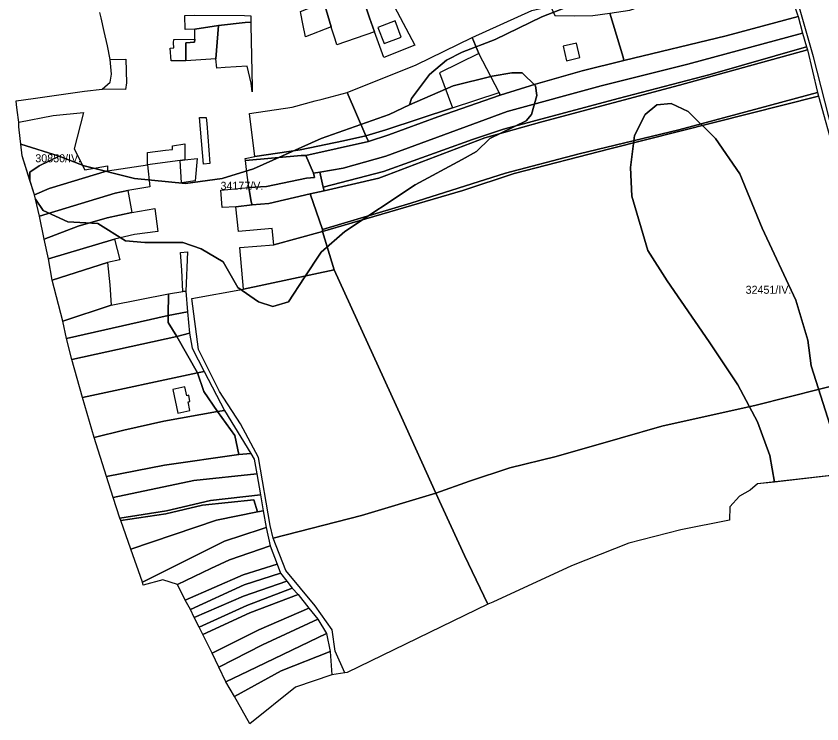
# Model space of a CAD drawing. Extents: x -532083 to -529270, y -1180561 to -1176456.
# Drawn here: x -532083 to -531579, y -1178876 to -1178433 of the extents above; entities that cross this region are included whole.
import ezdxf

# ---------------------------------------------------------------- set-up
doc = ezdxf.new("R2010")
doc.units = 0
for name, color, linetype in [('95560013', 7, 'Continuous'), ('95590013', 7, 'Continuous'), ('95610013', 7, 'Continuous'), ('95660013', 7, 'Continuous')]:
    doc.layers.add(name, color=color, linetype=linetype)

msp = doc.modelspace()

# ---------------------------------------------------------------- linework, layer by layer
at = {"layer": '95560013'}
for points in [[(-531547.8033, -1178576.86445), (-531567.7783, -1178522.58045), (-531572.5603, -1178505.32245), (-531584.2383, -1178458.86945), (-531591.8903, -1178432.61345), (-531602.2653, -1178396.57645), (-531604.7423, -1178392.64145), (-531576.9383, -1178389.59645), (-531567.2013, -1178431.02045), (-531545.1963, -1178517.96245), (-531535.0483, -1178553.58645), (-531517.1773, -1178614.23745), (-531494.4363, -1178669.65645), (-531470.1583, -1178727.24745), (-531454.4793, -1178763.65545), (-531462.1273, -1178770.74145), (-531480.8163, -1178726.71045), (-531489.0293, -1178711.65445), (-531517.1343, -1178652.33845), (-531534.5643, -1178611.81145)], [(-531852.9093, -1178459.31445), (-531858.6763, -1178443.37145), (-531861.7713, -1178434.62345), (-531867.5383, -1178417.26945), (-531854.3163, -1178412.33045), (-531846.4393, -1178427.28645), (-531833.4983, -1178451.69545)], [(-531841.9533, -1178446.51645), (-531845.8643, -1178436.42445), (-531856.5143, -1178440.55245), (-531852.6033, -1178450.64345)], [(-531797.4043, -1178510.54745), (-531853.1373, -1178530.52845), (-531890.7863, -1178540.43245), (-531892.7783, -1178531.04145), (-531878.3643, -1178528.46845), (-531851.6523, -1178520.96645), (-531793.2423, -1178499.53045), (-531775.7903, -1178493.10045), (-531717.0233, -1178477.02345), (-531662.8873, -1178463.44745), (-531591.1313, -1178444.14245), (-531588.6623, -1178452.67145), (-531648.9653, -1178470.01645), (-531706.5083, -1178484.98045), (-531778.1553, -1178504.03645)], [(-531836.0783, -1178550.36045), (-531891.1843, -1178566.80545), (-531898.9533, -1178544.62845), (-531890.1883, -1178542.63045), (-531856.0473, -1178534.79445), (-531850.8993, -1178532.77445), (-531789.7483, -1178509.55845), (-531754.0303, -1178499.60645), (-531668.0423, -1178476.71645), (-531588.1143, -1178454.59745), (-531581.8053, -1178481.28545), (-531618.1033, -1178490.98145), (-531668.4963, -1178504.43445), (-531730.7163, -1178519.44845), (-531776.7933, -1178531.51845)], [(-531905.1193, -1178517.08045), (-531933.4183, -1178521.18745), (-531936.7993, -1178494.40745), (-531910.1023, -1178490.30145), (-531895.6863, -1178486.37445), (-531891.4143, -1178485.30245), (-531875.7613, -1178481.16445), (-531864.0383, -1178508.23145), (-531878.0653, -1178511.36845)], [(-531774.0273, -1178715.80545), (-531799.2343, -1178724.04445), (-531820.4623, -1178731.61145), (-531841.8493, -1178684.12545), (-531883.8143, -1178591.98045), (-531891.1843, -1178568.00445), (-531803.5013, -1178542.41145), (-531771.5103, -1178531.81345), (-531711.5453, -1178516.50245), (-531581.2573, -1178483.48645), (-531560.8443, -1178556.78845), (-531548.5463, -1178586.00545), (-531524.2743, -1178648.65845), (-531560.8503, -1178661.55945), (-531620.2603, -1178676.52945), (-531679.0953, -1178689.77145), (-531705.2123, -1178697.25645), (-531745.1383, -1178708.70345)], [(-531965.6323, -1178526.00745), (-531968.1243, -1178496.72845), (-531963.8523, -1178496.72845), (-531963.4963, -1178500.65645), (-531961.5393, -1178525.65045)], [(-531890.1883, -1178542.63045), (-531898.9533, -1178544.62845), (-531924.6473, -1178550.62145), (-531935.2043, -1178551.42145), (-531935.8023, -1178549.62245), (-531937.1963, -1178540.63245), (-531926.2413, -1178540.03245), (-531901.1443, -1178534.83745), (-531896.1643, -1178534.23845), (-531896.7613, -1178531.64145), (-531892.7783, -1178531.04145), (-531890.7863, -1178540.43245)], [(-531935.2043, -1178551.42145), (-531945.3633, -1178552.61945), (-531953.8683, -1178552.99945), (-531954.6583, -1178542.25345), (-531937.1963, -1178540.63245), (-531935.8023, -1178549.62245)], [(-531883.8143, -1178591.98045), (-531940.5823, -1178604.16745), (-531942.7733, -1178577.99445), (-531921.6603, -1178576.39545), (-531891.1843, -1178568.00445)], [(-531987.5833, -1178620.60945), (-532051.2263, -1178634.89945), (-532053.5293, -1178624.00745), (-532023.2493, -1178614.05745), (-531987.5393, -1178606.94645)], [(-531975.6063, -1178618.17645), (-531987.5833, -1178620.60945), (-531987.5393, -1178606.94645), (-531978.5783, -1178605.47045), (-531976.5723, -1178605.33645)], [(-531982.2773, -1178633.68745), (-531987.5833, -1178624.86745), (-531987.5833, -1178620.60945), (-531975.6063, -1178618.17645), (-531974.2423, -1178631.71045)], [(-531982.2773, -1178633.68745), (-532047.9363, -1178648.10045), (-532051.2263, -1178634.89945), (-531987.5833, -1178620.60945), (-531987.5833, -1178624.86745)], [(-531969.3903, -1178656.49845), (-532041.2583, -1178671.72145), (-532047.9363, -1178648.10045), (-531982.2773, -1178633.68745)], [(-531735.5853, -1178777.07045), (-531784.7043, -1178799.66545), (-531787.9603, -1178801.02645), (-531802.3493, -1178770.63545), (-531820.4623, -1178731.61145), (-531799.2343, -1178724.04445), (-531774.0273, -1178715.80545), (-531745.1383, -1178708.70345), (-531705.2123, -1178697.25645), (-531679.0953, -1178689.77145), (-531620.2603, -1178676.52945), (-531560.8503, -1178661.55945), (-531524.2743, -1178648.65845), (-531494.4093, -1178711.65445), (-531619.2903, -1178725.85845), (-531623.8203, -1178729.83545), (-531630.6173, -1178733.52845), (-531636.5633, -1178740.06145), (-531636.8473, -1178748.58345), (-531667.1463, -1178754.54945), (-531699.7633, -1178762.91345)], [(-532015.2983, -1178692.15745), (-532033.9303, -1178696.89445), (-532041.2583, -1178671.72145), (-531969.3903, -1178656.49845), (-531965.3283, -1178668.02345), (-531956.8683, -1178680.48845), (-531990.4453, -1178686.58745)], [(-531981.5183, -1178681.52145), (-531974.0463, -1178679.92845), (-531975.1943, -1178674.54045), (-531974.0173, -1178674.28945), (-531974.8343, -1178670.45745), (-531976.0473, -1178670.71545), (-531977.2273, -1178665.18145), (-531984.6633, -1178666.76645)], [(-531989.9163, -1178714.16845), (-532026.1583, -1178721.17545), (-532033.9303, -1178696.89445), (-532015.2983, -1178692.15745), (-531990.4453, -1178686.58745), (-531956.8683, -1178680.48845), (-531946.0283, -1178695.60445), (-531943.3843, -1178707.53845)], [(-531971.6733, -1178723.71645), (-532021.9383, -1178734.31845), (-532026.1583, -1178721.17545), (-531989.9163, -1178714.16845), (-531943.3843, -1178707.53845), (-531935.9813, -1178706.74345), (-531933.8663, -1178710.45645), (-531932.2803, -1178719.47245)], [(-531961.0983, -1178736.18045), (-531988.5943, -1178742.54545), (-532017.8143, -1178747.18445), (-532021.9383, -1178734.31845), (-531971.6733, -1178723.71645), (-531932.2803, -1178719.47245), (-531929.9003, -1178732.73345)], [(-531931.7793, -1178743.24245), (-531957.4483, -1178748.54345), (-532011.0023, -1178766.68145), (-532017.2133, -1178748.59145), (-531989.1573, -1178744.50445), (-531966.2563, -1178739.20345), (-531934.0443, -1178735.66945)], [(-531952.4153, -1178761.66945), (-531976.5743, -1178773.78645), (-532003.7893, -1178787.18245), (-532011.0023, -1178766.68145), (-531957.4483, -1178748.54345), (-531931.7793, -1178743.24245), (-531928.2563, -1178742.73745), (-531926.4953, -1178753.08745), (-531929.5143, -1178754.09645)], [(-531960.9383, -1178778.74245), (-531981.7493, -1178788.58945), (-531990.9663, -1178785.77545), (-532003.1883, -1178789.19245), (-532003.7893, -1178787.18245), (-531976.5743, -1178773.78645), (-531952.4153, -1178761.66945), (-531929.5143, -1178754.09645), (-531926.4953, -1178753.08745), (-531923.9783, -1178764.44645), (-531949.3953, -1178773.28145)], [(-531919.4483, -1178776.05845), (-531940.8393, -1178782.62145), (-531976.9553, -1178798.42145), (-531981.7493, -1178788.58945), (-531960.9383, -1178778.74245), (-531949.3953, -1178773.28145), (-531923.9783, -1178764.44645)], [(-531940.0843, -1178788.93145), (-531973.6823, -1178804.37345), (-531976.9553, -1178798.42145), (-531940.8393, -1178782.62145), (-531919.4483, -1178776.05845), (-531917.4353, -1178781.61145)], [(-531940.5873, -1178795.99945), (-531971.4313, -1178809.29945), (-531973.6823, -1178804.37345), (-531940.0843, -1178788.93145), (-531917.4353, -1178781.61145), (-531913.4093, -1178786.66045)], [(-531968.3623, -1178815.25145), (-531971.4313, -1178809.29945), (-531940.5873, -1178795.99945), (-531913.4093, -1178786.66045), (-531910.1373, -1178790.95145), (-531938.5743, -1178801.80545)], [(-531965.9073, -1178819.97245), (-531968.3623, -1178815.25145), (-531938.5743, -1178801.80545), (-531910.1373, -1178790.95145), (-531906.3623, -1178794.99045), (-531936.5613, -1178806.34945)], [(-531960.1783, -1178831.67145), (-531965.9073, -1178819.97245), (-531936.5613, -1178806.34945), (-531906.3623, -1178794.99045), (-531899.8193, -1178803.57245), (-531931.0243, -1178816.95145)], [(-531956.0863, -1178840.29145), (-531960.1783, -1178831.67145), (-531931.0243, -1178816.95145), (-531899.8193, -1178803.57245), (-531894.0313, -1178810.38845), (-531928.7593, -1178826.29145)], [(-531956.0863, -1178840.29145), (-531928.7593, -1178826.29145), (-531894.0313, -1178810.38845), (-531888.7463, -1178819.22345), (-531937.5673, -1178842.95145), (-531951.5853, -1178849.52745)], [(-531937.5673, -1178842.95145), (-531888.7463, -1178819.22345), (-531886.4813, -1178830.58245), (-531916.9323, -1178842.69945), (-531946.2653, -1178858.76345), (-531951.5853, -1178849.52745)], [(-531946.2653, -1178858.76345), (-531916.9323, -1178842.69945), (-531886.4813, -1178830.58245), (-531885.2943, -1178845.21745), (-531908.0053, -1178852.81145), (-531936.6493, -1178875.79945)]]:
    msp.add_lwpolyline(points, close=True, dxfattribs=at)
at = {"layer": '95590013'}
for points in [[(-531638.8773, -1178445.75845), (-531702.8643, -1178461.11745), (-531703.3483, -1178459.17745), (-531711.5683, -1178431.53145), (-531699.1573, -1178429.75345), (-531687.7133, -1178425.87345), (-531675.7863, -1178421.83145), (-531658.7493, -1178415.49345), (-531643.1323, -1178409.09145), (-531627.1083, -1178403.91545), (-531605.9233, -1178397.92145), (-531594.6293, -1178432.08645), (-531593.8693, -1178433.61245)], [(-531885.8243, -1178440.12545), (-531889.9033, -1178426.01645), (-531890.4663, -1178424.88845), (-531867.5383, -1178417.26945), (-531861.7713, -1178434.62345), (-531858.6763, -1178443.37145), (-531882.1343, -1178451.37245), (-531883.2923, -1178447.78345), (-531885.2613, -1178441.67745)], [(-531901.8593, -1178446.33445), (-531903.4343, -1178438.26145), (-531904.6723, -1178431.80145), (-531904.9533, -1178430.53145), (-531890.4663, -1178424.88845), (-531889.9033, -1178426.01645), (-531885.8243, -1178440.12545)], [(-531702.8643, -1178461.11745), (-531728.8983, -1178467.63045), (-531758.0933, -1178476.06145), (-531780.2113, -1178482.93945), (-531780.8753, -1178481.16445), (-531793.4823, -1178456.75945), (-531797.6843, -1178446.77645), (-531760.3053, -1178429.91445), (-531748.6383, -1178427.32845), (-531745.8983, -1178433.14845), (-531733.9713, -1178433.31045), (-531722.2053, -1178432.98645), (-531711.5683, -1178431.53145), (-531703.3483, -1178459.17745)], [(-531956.2163, -1178439.34245), (-531971.0443, -1178441.67145), (-531977.1213, -1178441.73145), (-531977.2733, -1178433.09545), (-531971.4903, -1178432.94645), (-531939.9043, -1178433.09545), (-531936.0483, -1178433.24445), (-531936.0483, -1178437.26045), (-531939.6073, -1178437.40845)], [(-531591.1313, -1178444.14245), (-531662.8873, -1178463.44745), (-531717.0233, -1178477.02345), (-531775.7903, -1178493.10045), (-531793.2423, -1178499.53045), (-531851.6523, -1178520.96645), (-531878.3643, -1178528.46845), (-531892.7783, -1178531.04145), (-531896.7613, -1178531.64145), (-531901.5423, -1178520.65245), (-531862.4903, -1178511.78145), (-531849.6623, -1178507.56545), (-531819.1393, -1178496.47245), (-531780.2113, -1178482.93945), (-531758.0933, -1178476.06145), (-531728.8983, -1178467.63045), (-531702.8643, -1178461.11745), (-531638.8773, -1178445.75845), (-531593.8693, -1178433.61245)], [(-531957.9013, -1178460.06245), (-531976.6883, -1178461.30845), (-531976.6883, -1178450.09445), (-531971.0993, -1178449.78345), (-531970.9833, -1178447.89745), (-531971.0443, -1178441.67145), (-531956.2163, -1178439.34245)], [(-531938.3343, -1178464.73245), (-531952.0643, -1178465.50445), (-531957.3253, -1178465.89045), (-531957.9013, -1178460.06245), (-531956.2163, -1178439.34245), (-531939.6073, -1178437.40845), (-531936.0483, -1178437.26045), (-531936.0063, -1178439.06445), (-531935.0913, -1178477.93645), (-531935.0913, -1178480.71745), (-531935.8473, -1178475.40845)], [(-531809.8493, -1178490.70445), (-531851.6523, -1178504.45945), (-531864.0383, -1178508.23145), (-531875.7613, -1178481.16445), (-531832.6313, -1178463.85945), (-531797.6843, -1178446.77645), (-531793.4823, -1178456.75945), (-531818.0333, -1178468.96245)], [(-531976.6883, -1178461.30845), (-531985.8493, -1178461.30845), (-531986.3153, -1178453.52145), (-531984.1413, -1178453.36545), (-531984.2963, -1178450.25045), (-531984.2093, -1178448.02745), (-531970.9833, -1178447.89745), (-531971.0993, -1178449.78345), (-531976.6883, -1178450.09445)], [(-531738.6303, -1178461.41845), (-531730.2923, -1178459.39145), (-531732.5033, -1178450.29545), (-531740.8413, -1178452.32245)], [(-532014.3303, -1178479.26545), (-532028.8773, -1178479.10845), (-532023.9863, -1178474.68045), (-532023.1513, -1178469.65345), (-532023.8673, -1178460.55845), (-532014.0473, -1178460.31845), (-532013.7863, -1178475.21845)], [(-532025.4953, -1178530.14745), (-532061.9303, -1178541.24845), (-532071.0983, -1178545.25545), (-532078.9283, -1178520.83645), (-532080.9713, -1178502.73445), (-532080.9713, -1178499.83145), (-532059.5473, -1178495.65045), (-532040.4783, -1178493.77145), (-532046.4373, -1178516.31445), (-532039.7973, -1178529.63545), (-532025.6653, -1178527.07345)], [(-531980.0923, -1178523.59945), (-532000.5373, -1178526.43645), (-532000.5473, -1178521.09345), (-532000.4673, -1178518.70545), (-531989.2273, -1178517.27245), (-531984.8773, -1178516.83645), (-531984.8773, -1178514.43645), (-531977.2643, -1178513.34545), (-531977.2643, -1178523.38145)], [(-531970.7393, -1178536.47245), (-531979.2223, -1178537.56245), (-531980.0923, -1178523.59945), (-531977.2643, -1178523.38145), (-531969.4343, -1178522.50845)], [(-531901.1443, -1178534.83745), (-531926.2413, -1178540.03245), (-531937.1963, -1178540.63245), (-531938.4013, -1178531.18445), (-531939.2913, -1178523.68645), (-531904.5303, -1178520.65245), (-531901.5423, -1178520.65245), (-531896.7613, -1178531.64145), (-531896.1643, -1178534.23845)], [(-532020.7653, -1178544.10845), (-532068.0013, -1178558.59245), (-532071.0983, -1178545.25545), (-532061.9303, -1178541.24845), (-532025.4953, -1178530.14745), (-532000.5373, -1178526.43645), (-531999.0723, -1178540.15745), (-532012.8223, -1178542.37745)], [(-532025.7683, -1178559.59845), (-532043.8213, -1178564.83445), (-532065.2343, -1178572.86745), (-532068.0013, -1178558.59245), (-532020.7653, -1178544.10845), (-532012.8223, -1178542.37745), (-532010.4523, -1178556.17045)], [(-531891.1843, -1178568.00445), (-531921.6603, -1178576.39545), (-531922.6563, -1178566.20645), (-531943.7693, -1178568.00445), (-531945.3633, -1178552.61945), (-531935.2043, -1178551.42145), (-531924.6473, -1178550.62145), (-531898.9533, -1178544.62845), (-531891.1843, -1178566.80545)], [(-532021.2003, -1178572.90745), (-532062.4673, -1178585.16045), (-532065.2343, -1178572.86745), (-532043.8213, -1178564.83445), (-532025.7683, -1178559.59845), (-532010.4523, -1178556.17045), (-531995.9113, -1178553.79245), (-531994.0123, -1178568.10745), (-532008.5853, -1178569.85245)], [(-532025.5233, -1178587.49345), (-532060.0953, -1178598.44445), (-532062.4673, -1178585.16045), (-532021.2003, -1178572.90745), (-532017.9383, -1178585.77945)], [(-531979.1133, -1178592.32345), (-531979.8743, -1178581.19745), (-531975.5243, -1178580.76145), (-531976.5723, -1178605.33645), (-531978.5783, -1178605.47045)], [(-532023.2493, -1178614.05745), (-532053.5293, -1178624.00745), (-532060.0953, -1178598.44445), (-532025.5233, -1178587.49345), (-532024.1853, -1178601.44645)]]:
    msp.add_lwpolyline(points, close=True, dxfattribs=at)
at = {"layer": '95610013'}
for points in [[(-531850.8993, -1178532.77445), (-531856.0473, -1178534.79445), (-531890.1883, -1178542.63045), (-531890.7863, -1178540.43245), (-531853.1373, -1178530.52845), (-531797.4043, -1178510.54745), (-531778.1553, -1178504.03645), (-531706.5083, -1178484.98045), (-531648.9653, -1178470.01645), (-531588.6623, -1178452.67145), (-531588.1143, -1178454.59745), (-531668.0423, -1178476.71645), (-531754.0303, -1178499.60645), (-531789.7483, -1178509.55845)], [(-531771.5103, -1178531.81345), (-531803.5013, -1178542.41145), (-531891.1843, -1178568.00445), (-531891.1843, -1178566.80545), (-531836.0783, -1178550.36045), (-531776.7933, -1178531.51845), (-531730.7163, -1178519.44845), (-531668.4963, -1178504.43445), (-531618.1033, -1178490.98145), (-531581.8053, -1178481.28545), (-531581.2573, -1178483.48645), (-531711.5453, -1178516.50245)], [(-531862.4903, -1178511.78145), (-531864.0383, -1178508.23145), (-531851.6523, -1178504.45945), (-531809.8493, -1178490.70445), (-531780.8753, -1178481.16445), (-531780.2113, -1178482.93945), (-531819.1393, -1178496.47245), (-531849.6623, -1178507.56545)], [(-531862.4903, -1178511.78145), (-531901.5423, -1178520.65245), (-531904.5303, -1178520.65245), (-531939.2913, -1178523.68645), (-531939.4693, -1178522.43645), (-531933.4183, -1178521.18745), (-531905.1193, -1178517.08045), (-531878.0653, -1178511.36845), (-531864.0383, -1178508.23145)], [(-531866.7653, -1178745.56645), (-531921.9973, -1178759.72845), (-531923.8653, -1178751.81445), (-531931.2863, -1178709.21245), (-531942.3853, -1178688.18245), (-531955.6433, -1178668.07945), (-531968.5923, -1178641.79245), (-531972.8503, -1178609.96245), (-531940.5823, -1178604.16745), (-531883.8143, -1178591.98045), (-531841.8493, -1178684.12545), (-531820.4623, -1178731.61145)], [(-531969.3903, -1178656.49845), (-531982.2773, -1178633.68745), (-531974.2423, -1178631.71045), (-531972.7253, -1178640.98645), (-531965.1453, -1178655.58545)], [(-531956.8683, -1178680.48845), (-531965.3283, -1178668.02345), (-531969.3903, -1178656.49845), (-531965.1453, -1178655.58545), (-531952.3733, -1178679.95745)], [(-531935.9813, -1178706.74345), (-531943.3843, -1178707.53845), (-531946.0283, -1178695.60445), (-531956.8683, -1178680.48845), (-531952.3733, -1178679.95745)], [(-531928.2563, -1178742.73745), (-531931.7793, -1178743.24245), (-531934.0443, -1178735.66945), (-531966.2563, -1178739.20345), (-531989.1573, -1178744.50445), (-532017.2133, -1178748.59145), (-532017.8143, -1178747.18445), (-531988.5943, -1178742.54545), (-531961.0983, -1178736.18045), (-531929.9003, -1178732.73345)], [(-531787.9603, -1178801.02645), (-531875.8823, -1178843.78045), (-531877.3153, -1178843.98645), (-531883.2103, -1178830.33045), (-531885.2233, -1178816.95145), (-531895.7933, -1178802.05845), (-531914.1633, -1178779.84445), (-531921.9973, -1178759.72845), (-531866.7653, -1178745.56645), (-531820.4623, -1178731.61145), (-531802.3493, -1178770.63545)]]:
    msp.add_lwpolyline(points, close=True, dxfattribs=at)
at = {"layer": '95660013'}
for points in [[(-531711.1873, -1178417.00045), (-531754.1253, -1178434.00045), (-531783.3753, -1178448.00045), (-531803.8123, -1178456.00045), (-531813.6253, -1178461.00045), (-531824.3123, -1178470.00045), (-531835.6253, -1178485.00045), (-531836.8123, -1178489.00045), (-531849.5003, -1178495.00045), (-531892.0003, -1178510.00045), (-531934.3753, -1178529.00045), (-531954.0003, -1178535.00045), (-531976.8753, -1178538.00045), (-532008.6873, -1178535.00045), (-532040.1253, -1178527.00045), (-532055.6873, -1178521.00045), (-532079.7683, -1178513.39645), (-532080.9713, -1178502.73445), (-532080.9713, -1178499.83145), (-532081.9923, -1178492.14745), (-532082.3333, -1178488.73245), (-532082.6733, -1178486.34145), (-532071.9463, -1178484.85345), (-532039.8533, -1178480.42445), (-532028.8773, -1178479.10845), (-532023.9863, -1178474.68045), (-532023.1513, -1178469.65345), (-532023.8673, -1178460.55845), (-532025.6563, -1178452.06045), (-532027.6843, -1178443.08445), (-532029.5063, -1178434.54645), (-532030.3663, -1178431.20345)], [(-531569.6253, -1178703.00045), (-531585.8753, -1178652.00045), (-531587.8753, -1178636.00045), (-531595.3123, -1178611.00045), (-531616.5003, -1178566.00045), (-531630.3753, -1178532.00045), (-531645.5003, -1178510.00045), (-531662.6253, -1178493.00045), (-531673.3123, -1178488.00045), (-531682.1873, -1178489.00045), (-531689.6253, -1178495.00045), (-531696.1253, -1178508.00045), (-531698.6253, -1178528.00045), (-531697.8123, -1178546.00045), (-531687.8753, -1178580.00045), (-531675.6873, -1178599.00045), (-531649.6253, -1178637.00045), (-531631.6253, -1178664.00045), (-531619.3753, -1178687.00045), (-531611.6253, -1178708.00045), (-531608.6883, -1178724.65245), (-531619.2903, -1178725.85845), (-531623.8203, -1178729.83545), (-531630.6173, -1178733.52845), (-531636.5633, -1178740.06145), (-531636.8473, -1178748.58345), (-531667.1463, -1178754.54945), (-531699.7633, -1178762.91345), (-531735.5853, -1178777.07045), (-531784.7043, -1178799.66545), (-531787.9603, -1178801.02645), (-531875.8823, -1178843.78045), (-531877.3153, -1178843.98645), (-531885.2943, -1178845.21745), (-531908.0053, -1178852.81145), (-531936.6493, -1178875.79945), (-531946.2653, -1178858.76345), (-531951.5853, -1178849.52745), (-531956.0863, -1178840.29145), (-531960.1783, -1178831.67145), (-531965.9073, -1178819.97245), (-531968.3623, -1178815.25145), (-531971.4313, -1178809.29945), (-531973.6823, -1178804.37345), (-531976.9553, -1178798.42145), (-531981.7493, -1178788.58945), (-531990.9663, -1178785.77545), (-532003.1883, -1178789.19245), (-532003.7893, -1178787.18245), (-532011.0023, -1178766.68145), (-532017.2133, -1178748.59145), (-532017.8143, -1178747.18445), (-532021.9383, -1178734.31845), (-532026.1583, -1178721.17545), (-532033.9303, -1178696.89445), (-532041.2583, -1178671.72145), (-532047.9363, -1178648.10045), (-532051.2263, -1178634.89945), (-532053.5293, -1178624.00745), (-532060.0953, -1178598.44445), (-532062.4673, -1178585.16045), (-532065.2343, -1178572.86745), (-532068.0013, -1178558.59245), (-532070.4903, -1178547.87245), (-532065.8123, -1178555.00045), (-532050.3123, -1178562.00045), (-532031.6253, -1178563.00045), (-532014.3753, -1178574.00045), (-532002.1873, -1178575.00045), (-531978.5003, -1178575.00045), (-531967.1253, -1178579.00045), (-531953.1873, -1178587.00045), (-531944.1873, -1178603.00045), (-531931.1253, -1178612.00045), (-531922.1873, -1178615.00045), (-531912.3753, -1178612.00045), (-531902.6253, -1178597.00045), (-531892.0003, -1178581.00045), (-531877.3123, -1178568.00045), (-531833.1873, -1178539.00045), (-531803.8123, -1178523.00045), (-531794.8753, -1178518.00045), (-531786.6873, -1178510.00045), (-531763.8123, -1178499.00045), (-531760.6253, -1178495.00045), (-531757.3123, -1178483.00045), (-531758.1253, -1178477.00045), (-531766.3123, -1178469.00045), (-531772.8123, -1178469.00045), (-531785.1253, -1178471.00045), (-531809.6253, -1178477.00045), (-531836.8123, -1178489.00045), (-531835.6253, -1178485.00045), (-531824.3123, -1178470.00045), (-531813.6253, -1178461.00045), (-531803.8123, -1178456.00045), (-531783.3753, -1178448.00045), (-531754.1253, -1178434.00045), (-531711.1873, -1178417.00045)]]:
    msp.add_lwpolyline(points, dxfattribs=at)
for points in [[(-532065.8123, -1178555.00045), (-532070.4903, -1178547.87245), (-532071.0983, -1178545.25545), (-532074.0003, -1178536.20545), (-532074.0003, -1178531.00045), (-532068.3123, -1178527.00045), (-532055.6873, -1178521.00045), (-532040.1253, -1178527.00045), (-532008.6873, -1178535.00045), (-531976.8753, -1178538.00045), (-531954.0003, -1178535.00045), (-531934.3753, -1178529.00045), (-531892.0003, -1178510.00045), (-531849.5003, -1178495.00045), (-531836.8123, -1178489.00045), (-531809.6253, -1178477.00045), (-531785.1253, -1178471.00045), (-531772.8123, -1178469.00045), (-531766.3123, -1178469.00045), (-531758.1253, -1178477.00045), (-531757.3123, -1178483.00045), (-531760.6253, -1178495.00045), (-531763.8123, -1178499.00045), (-531786.6873, -1178510.00045), (-531794.8753, -1178518.00045), (-531803.8123, -1178523.00045), (-531833.1873, -1178539.00045), (-531877.3123, -1178568.00045), (-531892.0003, -1178581.00045), (-531902.6253, -1178597.00045), (-531912.3753, -1178612.00045), (-531922.1873, -1178615.00045), (-531931.1253, -1178612.00045), (-531944.1873, -1178603.00045), (-531953.1873, -1178587.00045), (-531967.1253, -1178579.00045), (-531978.5003, -1178575.00045), (-532002.1873, -1178575.00045), (-532014.3753, -1178574.00045), (-532031.6253, -1178563.00045), (-532050.3123, -1178562.00045)], [(-531554.9083, -1178718.53545), (-531608.6883, -1178724.65245), (-531611.6253, -1178708.00045), (-531619.3753, -1178687.00045), (-531631.6253, -1178664.00045), (-531649.6253, -1178637.00045), (-531675.6873, -1178599.00045), (-531687.8753, -1178580.00045), (-531697.8123, -1178546.00045), (-531698.6253, -1178528.00045), (-531696.1253, -1178508.00045), (-531689.6253, -1178495.00045), (-531682.1873, -1178489.00045), (-531673.3123, -1178488.00045), (-531662.6253, -1178493.00045), (-531645.5003, -1178510.00045), (-531630.3753, -1178532.00045), (-531616.5003, -1178566.00045), (-531595.3123, -1178611.00045), (-531587.8753, -1178636.00045), (-531585.8753, -1178652.00045), (-531569.6253, -1178703.00045)], [(-532074.0003, -1178536.20545), (-532078.9283, -1178520.83645), (-532079.7683, -1178513.39645), (-532055.6873, -1178521.00045), (-532068.3123, -1178527.00045), (-532074.0003, -1178531.00045)]]:
    msp.add_lwpolyline(points, close=True, dxfattribs=at)

# ---------------------------------------------------------------- texts
for s, rotation, p in [('30850/IV.', 360, (-532070.67064, -1178524.80095)), ('34177/V.', 0, (-531954.94701, -1178542.00045)), ('32451/IV.', 0, (-531626.7668, -1178606.98272))]:
    msp.add_text(s, height=5, rotation=rotation, dxfattribs=at).set_placement(p)

doc.saveas('drawing.dxf')
